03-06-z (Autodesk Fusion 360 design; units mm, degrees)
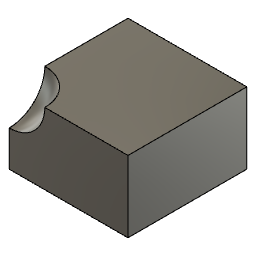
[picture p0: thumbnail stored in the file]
box_primitive "直方体プリミティブ" DistanceX 50 DistanceY 50 DistanceZ 30 OffsetDistanceX 0 OffsetDistanceY 0
sphere_primitive "球プリミティブ" Diameter 30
